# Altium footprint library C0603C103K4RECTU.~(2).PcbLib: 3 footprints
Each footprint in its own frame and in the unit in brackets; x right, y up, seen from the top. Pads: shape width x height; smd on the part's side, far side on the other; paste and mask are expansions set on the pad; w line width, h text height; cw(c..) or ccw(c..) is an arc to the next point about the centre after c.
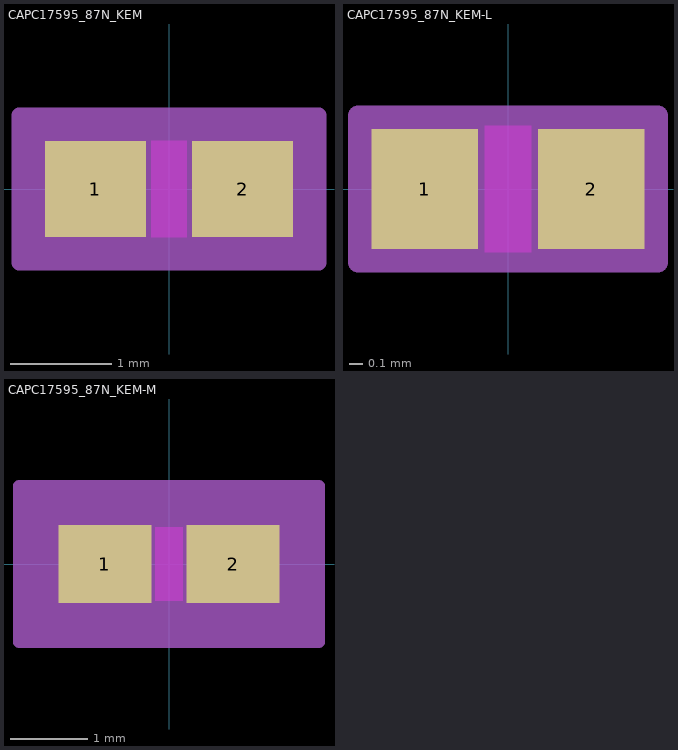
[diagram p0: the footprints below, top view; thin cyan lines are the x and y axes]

## CAPC17595_87N_KEM [mm]
pads (2):
  rect 1x0.95 smd paste+0 mask+0: 1(-0.725,0) 2(0.725,0)
Top Layer keep-out:
  region: -0.174,-0.424 -0.174,0.424 0.174,0.424 0.174,-0.424
Top Overlay:
  text ".Designator" at -3.492,-0.635 h1.27
Keep-Out Layer:
  region: -0.174,-0.475 -0.174,0.475 0.174,0.475 0.174,-0.475
Mechanical 13:
  lines w0.025: -0.875,-0.475 -0.875,0.475 ; -0.875,-0.475 0.875,-0.475 ; -0.875,-0.475 -0.375,-0.475 -0.375,0.475 -0.875,0.475 ; -0.875,-0.475 -0.875,0.475 ; -0.875,0.475 0.875,0.475 ; 0.875,-0.475 0.875,0.475 ; 0.875,-0.475 0.875,0.475 ; 0.875,-0.475 0.375,-0.475 0.375,0.475 0.875,0.475
  text ".Designator" at -3.492,-0.635 h1.27
Mechanical 15:
  region: 1.479,-0.729 -1.479,-0.729 -1.479,0.729 1.479,0.729
  lines w0.152: -1.479,-0.729 1.479,-0.729 1.479,0.729 -1.479,0.729 -1.479,-0.729
3D body "CAPC17595_87N_KEM.step": height 0.87, standoff 0, extent -0.875,-0.475 0.875,0.475

## CAPC17595_87N_KEM-L [mm]
pads (2):
  rect 0.8x0.9 smd paste+0 mask+0: 1(-0.625,0) 2(0.625,0)
Top Layer keep-out:
  region: -0.174,-0.424 -0.174,0.424 0.174,0.424 0.174,-0.424
Top Overlay:
  text ".Designator" at -3.492,-0.635 h1.27
Keep-Out Layer:
  region: -0.174,-0.475 -0.174,0.475 0.174,0.475 0.174,-0.475
Mechanical 13:
  lines w0.025: -0.875,-0.475 -0.875,0.475 ; -0.875,-0.475 -0.375,-0.475 -0.375,0.475 -0.875,0.475 ; -0.875,-0.475 0.875,-0.475 ; -0.875,-0.475 -0.875,0.475 ; -0.875,0.475 0.875,0.475 ; 0.875,-0.475 0.375,-0.475 0.375,0.475 0.875,0.475 ; 0.875,-0.475 0.875,0.475 ; 0.875,-0.475 0.875,0.475
  text ".Designator" at -3.492,-0.635 h1.27
Mechanical 15:
  region: 1.127,-0.552 -1.127,-0.552 -1.127,0.552 1.127,0.552
  lines w0.152: -1.127,-0.552 -1.127,0.552 1.127,0.552 1.127,-0.552 -1.127,-0.552
3D body "CAPC17595_87N_KEM.step": height 0.87, standoff 0, extent -0.875,-0.475 0.875,0.475

## CAPC17595_87N_KEM-M [mm]
pads (2):
  rect 1.2x1 smd paste+0 mask+0: 1(-0.825,0) 2(0.825,0)
Top Layer keep-out:
  region: -0.174,-0.424 -0.174,0.424 0.174,0.424 0.174,-0.424
Top Overlay:
  text ".Designator" at -3.492,-0.635 h1.27
Keep-Out Layer:
  region: -0.174,-0.475 -0.174,0.475 0.174,0.475 0.174,-0.475
Mechanical 13:
  lines w0.025: -0.875,-0.475 -0.875,0.475 ; -0.875,-0.475 -0.375,-0.475 -0.375,0.475 -0.875,0.475 ; -0.875,-0.475 0.875,-0.475 ; -0.875,-0.475 -0.875,0.475 ; -0.875,0.475 0.875,0.475 ; 0.875,-0.475 0.375,-0.475 0.375,0.475 0.875,0.475 ; 0.875,-0.475 0.875,0.475 ; 0.875,-0.475 0.875,0.475
  text ".Designator" at -3.492,-0.635 h1.27
Mechanical 15:
  region: 1.933,-1.008 -1.933,-1.008 -1.933,1.008 1.933,1.008
  lines w0.152: -1.933,-1.008 -1.933,1.008 1.933,1.008 1.933,-1.008 -1.933,-1.008
3D body "CAPC17595_87N_KEM.step": height 0.87, standoff 0, extent -0.875,-0.475 0.875,0.475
